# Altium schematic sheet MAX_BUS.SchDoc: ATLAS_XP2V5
size 558 x 431 mm; Organization: IMP Automatika d.o.o.; Revision: V5
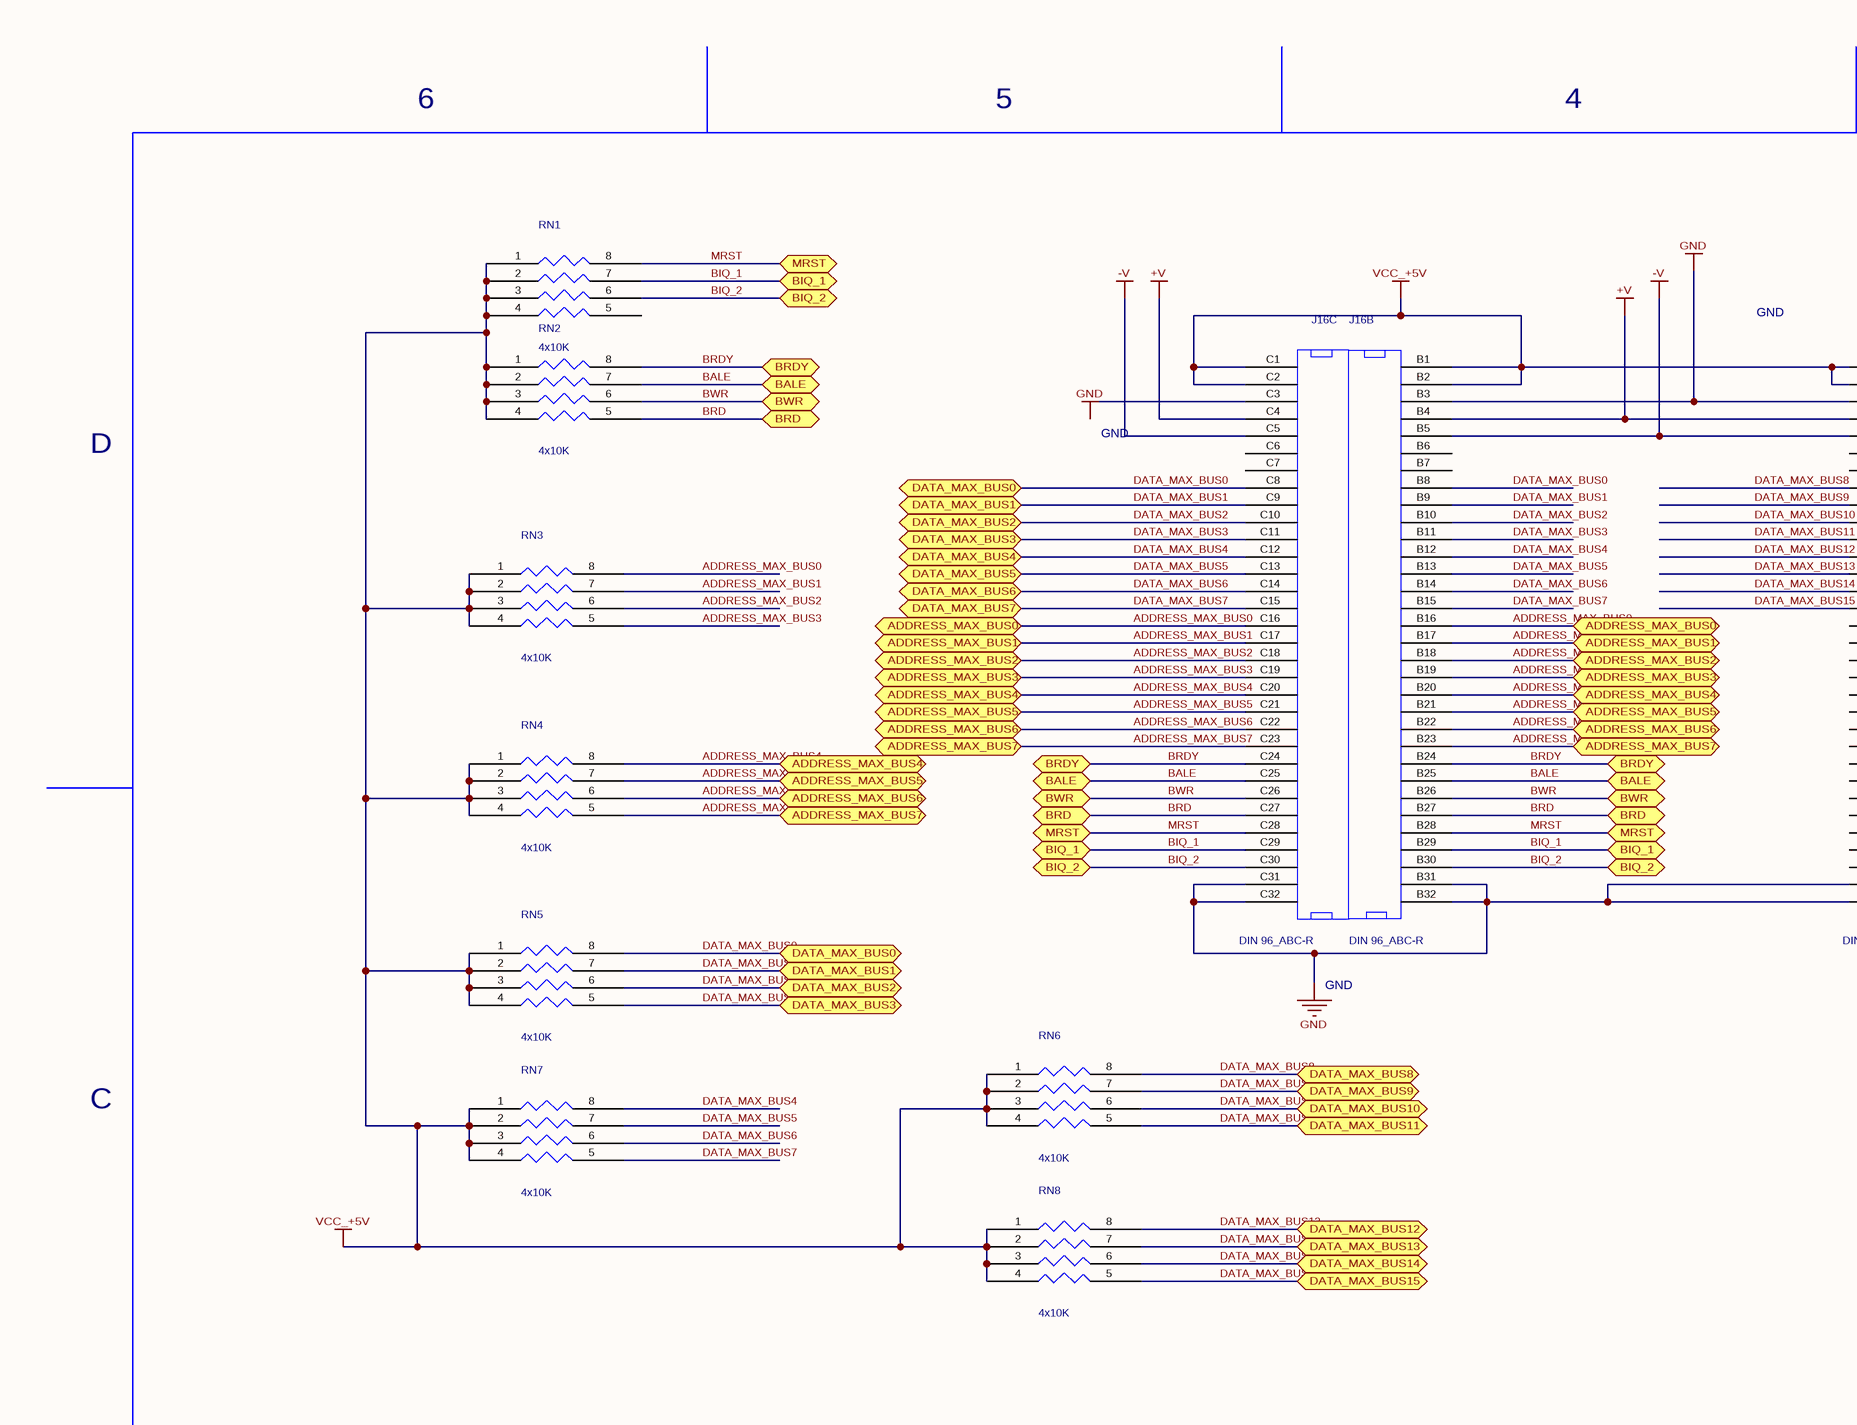
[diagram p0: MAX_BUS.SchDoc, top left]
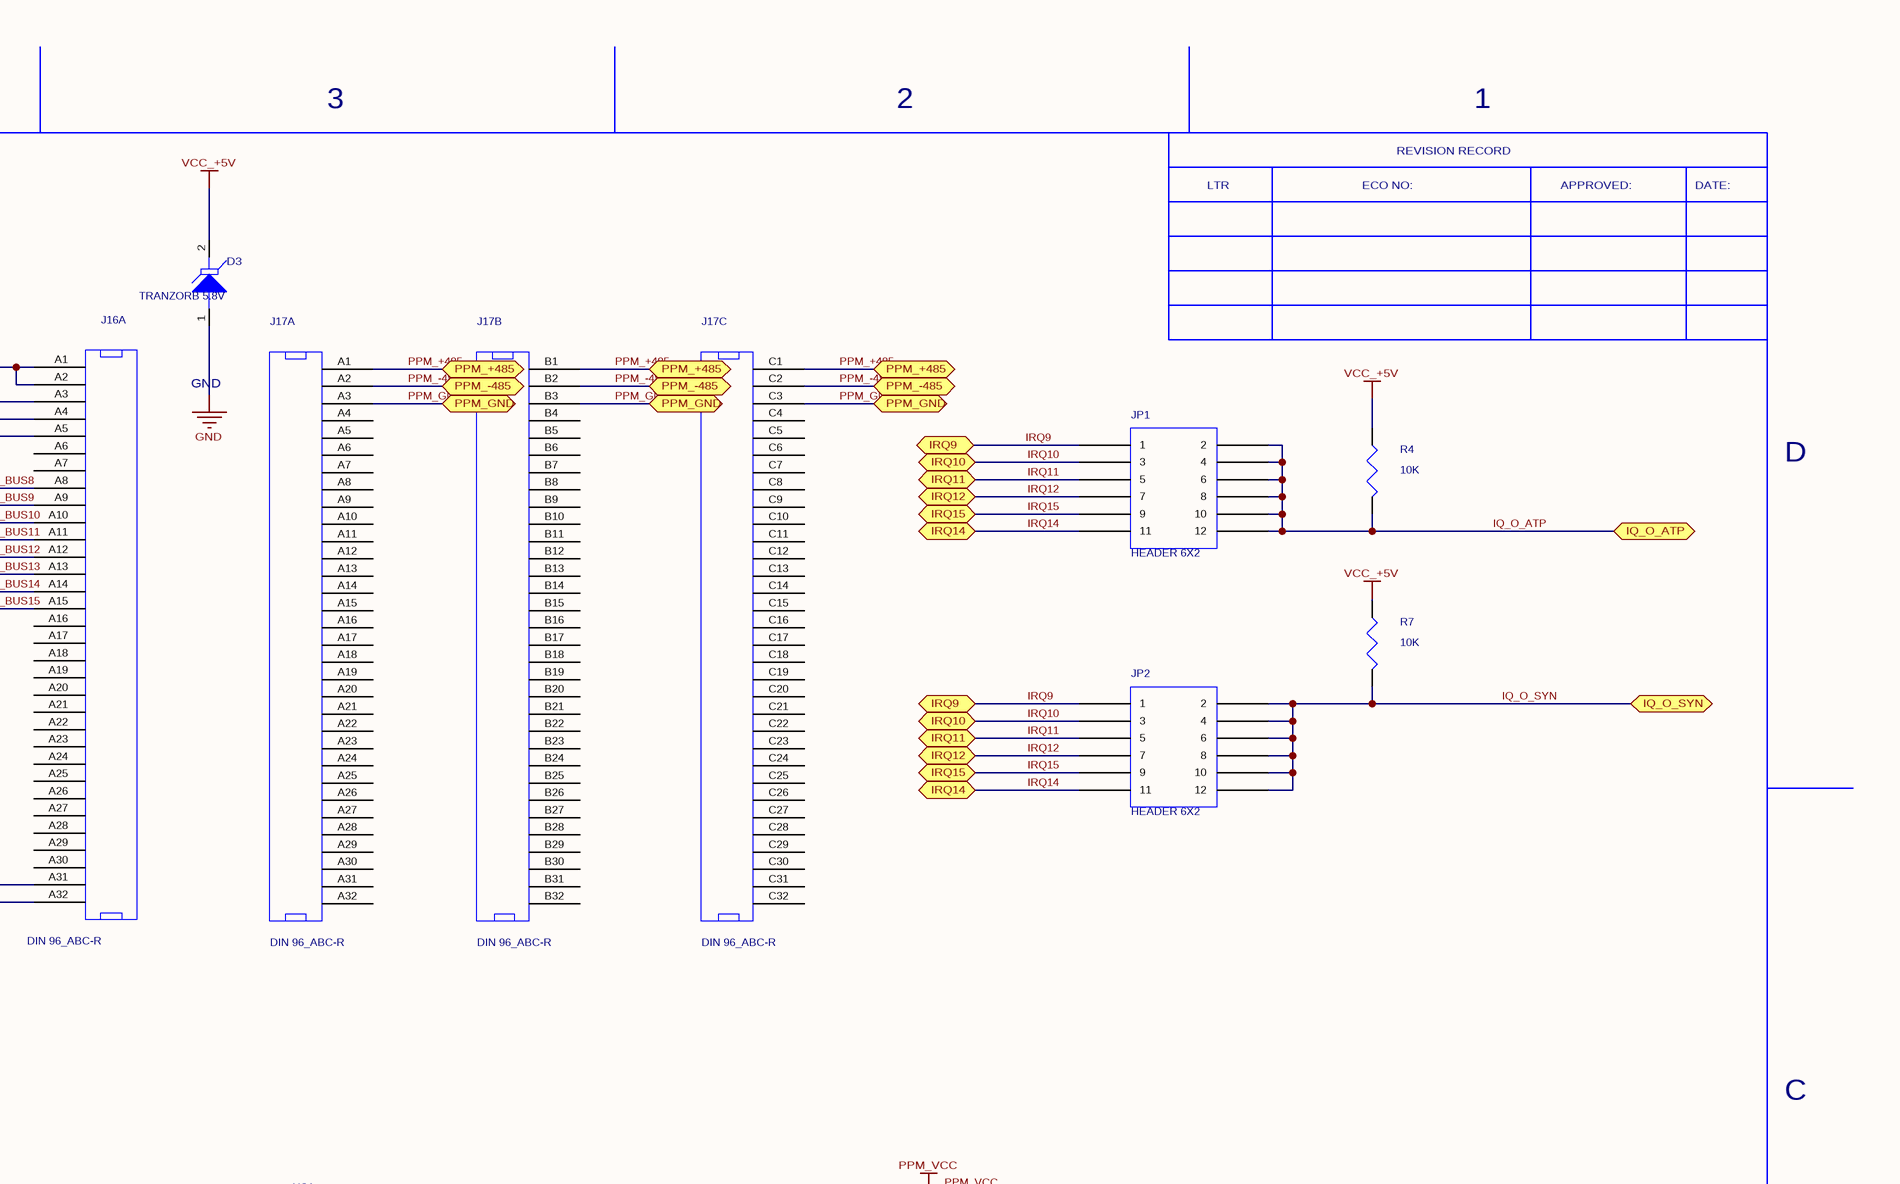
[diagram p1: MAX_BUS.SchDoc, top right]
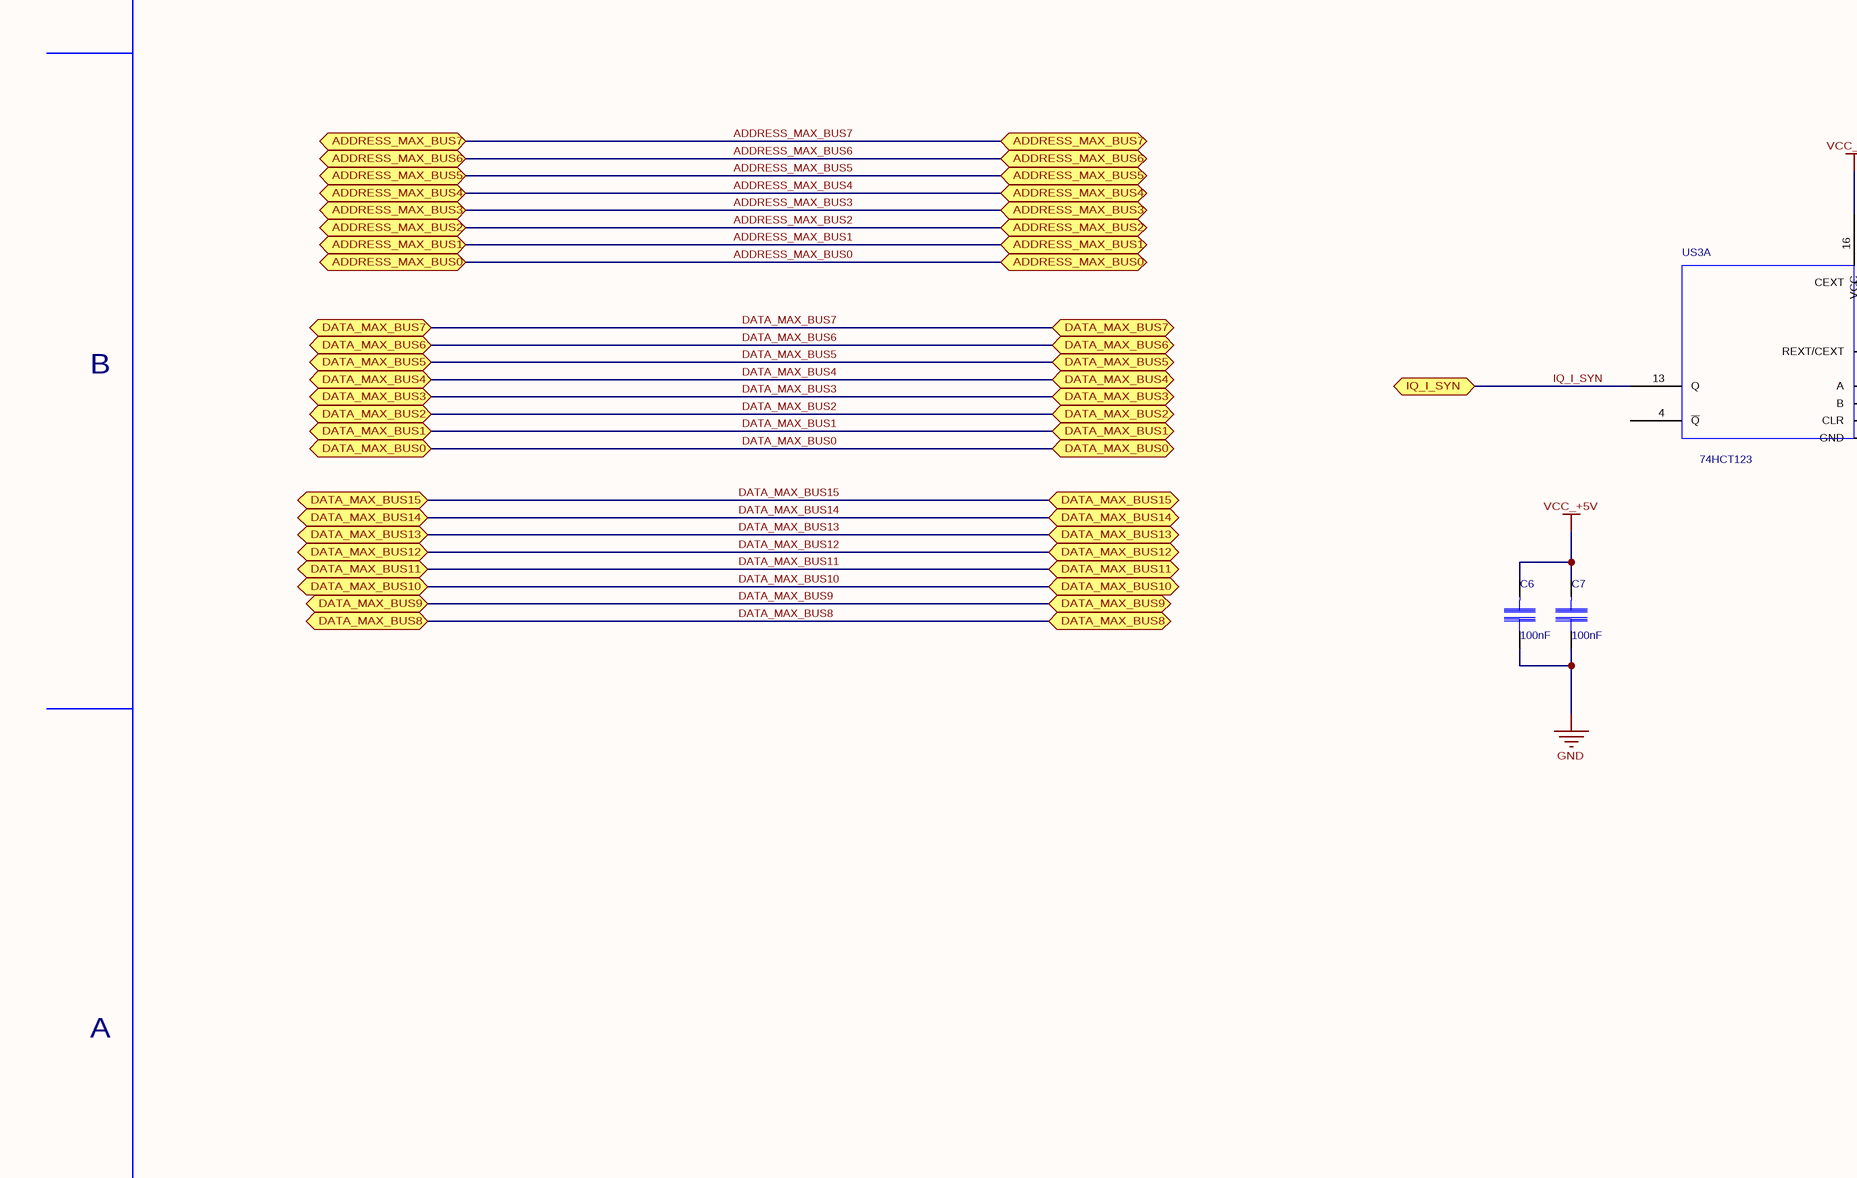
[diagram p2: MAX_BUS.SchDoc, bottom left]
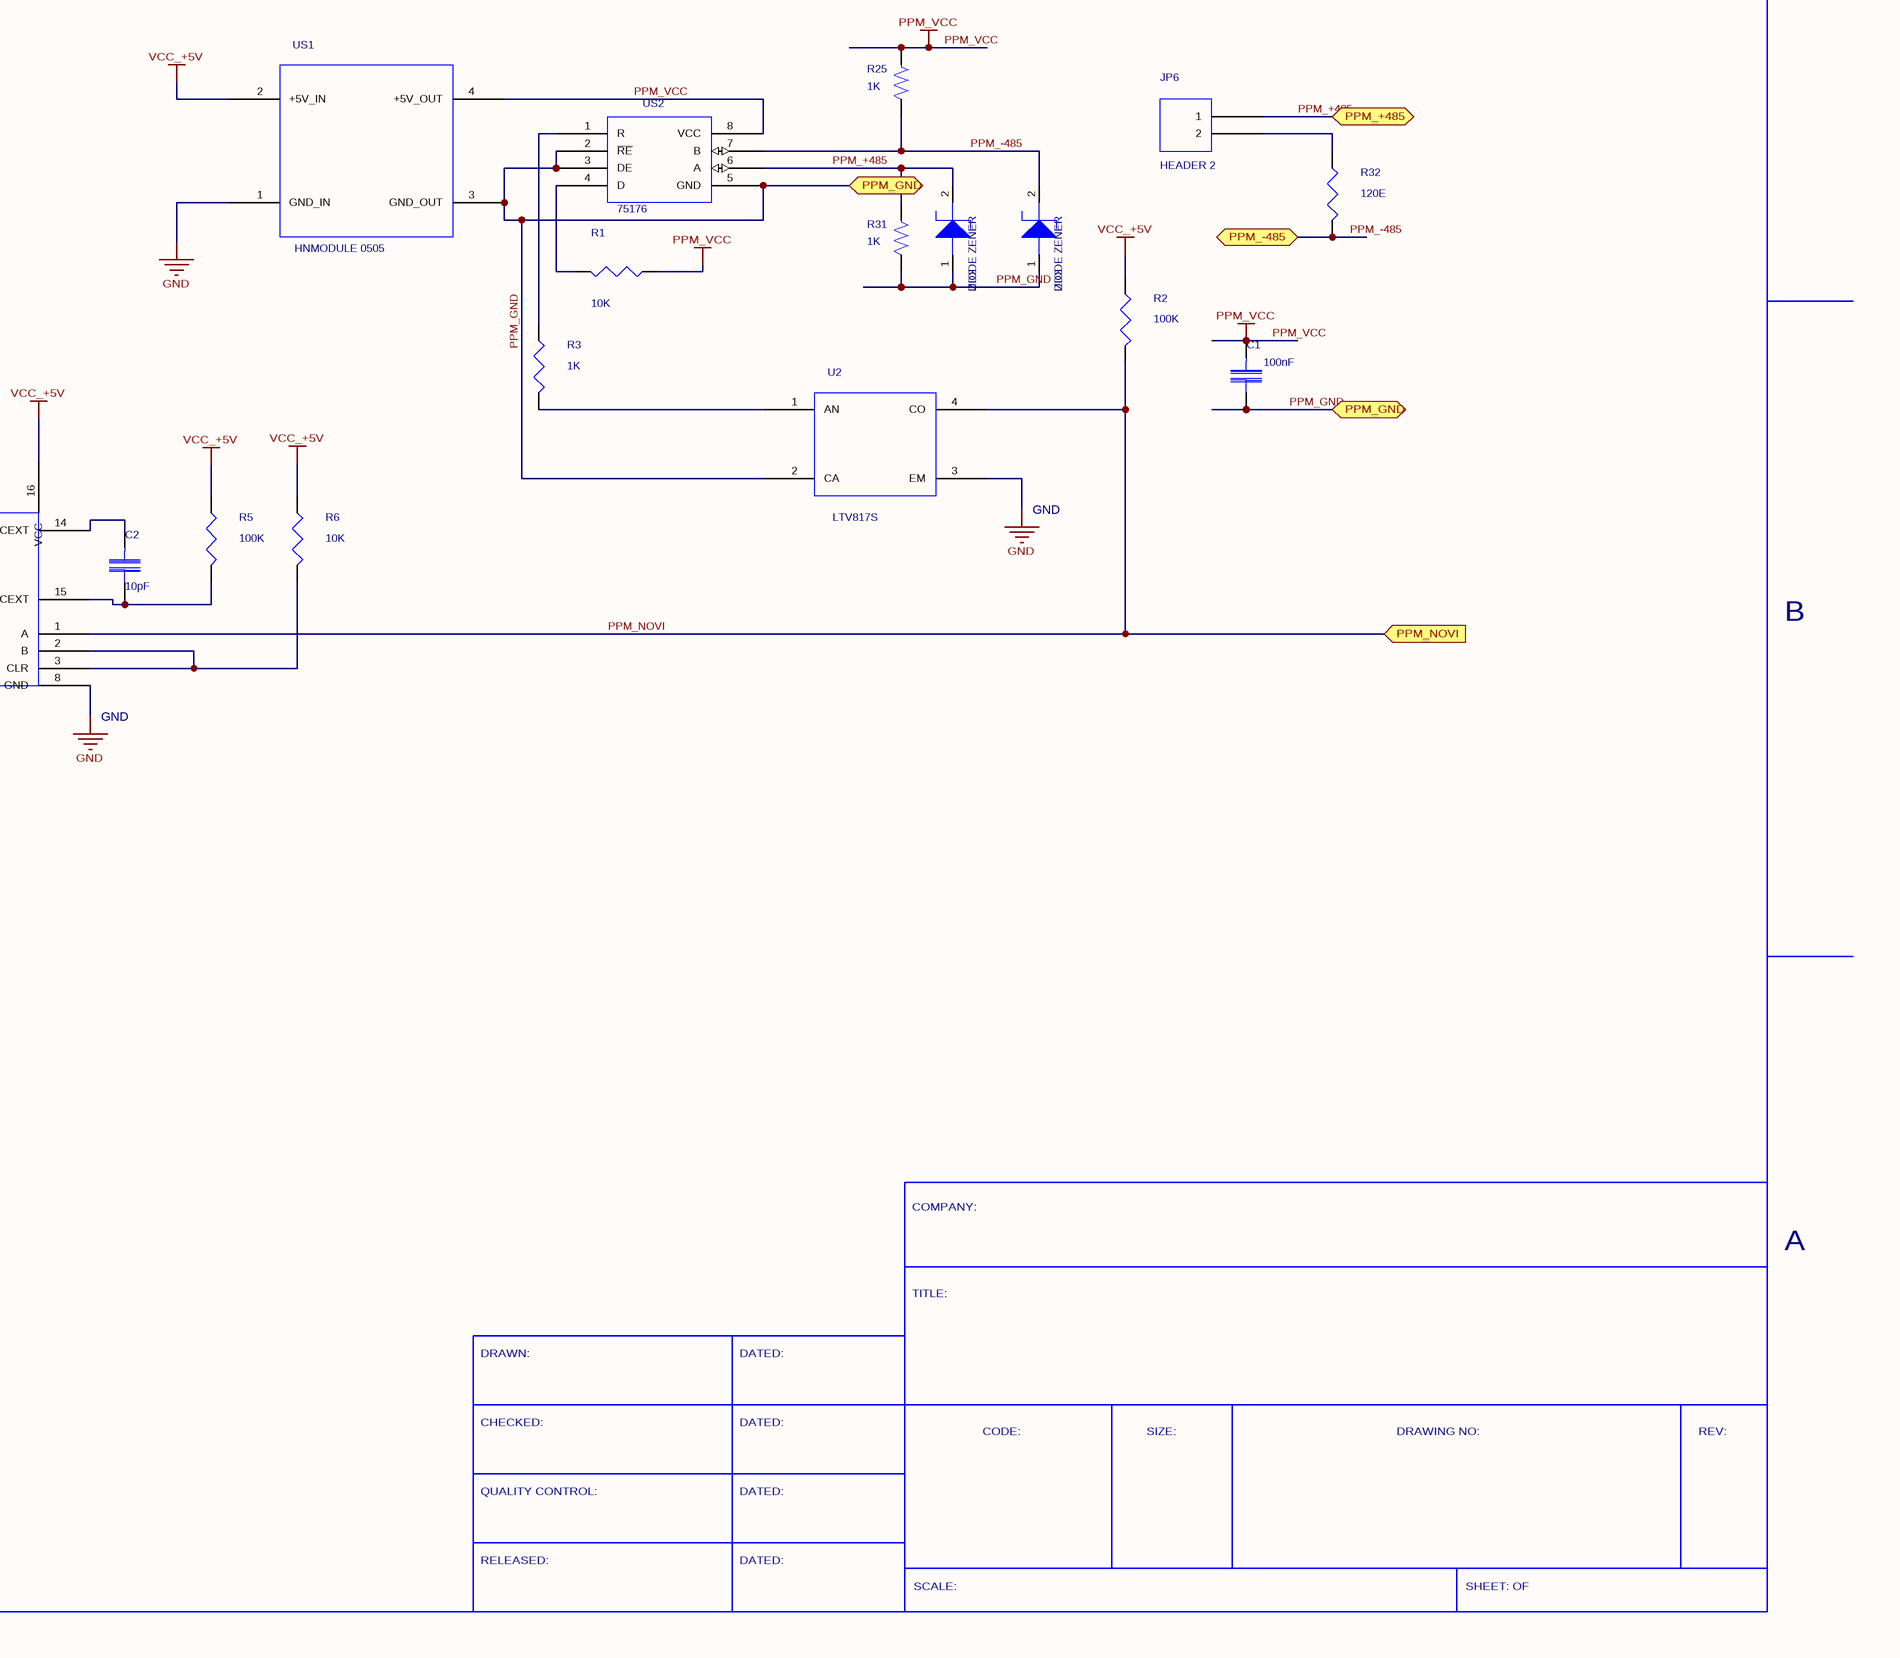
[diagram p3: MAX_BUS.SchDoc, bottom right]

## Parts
C1  value 100nF  [SM/C_0805]  (hidden comment: C)
C2  value 10pF  [SM/C_0805]  (hidden comment: C)
C6  value 100nF  [SM/C_0805]  (hidden comment: C)
C7  value 100nF  [SM/C_0805]  (hidden comment: C)
D3  value TRANZORB 5.8V  [SM/DO214AC_21]  (hidden comment: TRANZORB_0)
J16  value DIN 96_ABC-R  [DIN96_ABC/R]  (hidden comment: DIN_96_ABC-R)  (parts A,B,C of 3)
J17  value DIN 96_ABC-R  [DIN96_ABC/R]  (hidden comment: DIN_96_ABC-R)  (parts A,B,C of 3)
JP1  value HEADER 6X2  [BLKCON.100/VH/TM2OE/W.200/12]  (hidden comment: HEADER_6X2)
JP2  value HEADER 6X2  [BLKCON.100/VH/TM2OE/W.200/12]  (hidden comment: HEADER_6X2)
JP6  value HEADER 2  [JUMPER_100]  (hidden comment: HEADER_2)
R1  value 10K  [SM/R_1206]  (hidden comment: RESISTOR_2)
R2  value 100K  [SM/R_1206]  (hidden comment: RESISTOR_2)
R3  value 1K  [SM/R_1206]  (hidden comment: RESISTOR_2)
R4  value 10K  [SM/R_1206]  (hidden comment: RESISTOR_2)
R5  value 100K  [SM/R_1206]  (hidden comment: RESISTOR_2)
R6  value 10K  [SM/R_1206]  (hidden comment: RESISTOR_2)
R7  value 10K  [SM/R_1206]  (hidden comment: RESISTOR_2)
R25  value 1K  [SM/R_1206]  (hidden comment: R)
R31  value 1K  [SM/R_1206]  (hidden comment: R)
R32  value 120E  [SM/R_1206]  (hidden comment: RESISTOR_2)
RN1  value 4x10K  [SMD_RX4]  (hidden comment: RESAR_IS_4/SM)
RN2  value 4x10K  [SMD_RX4]  (hidden comment: RESAR_IS_4/SM)
RN3  value 4x10K  [SMD_RX4]  (hidden comment: RESAR_IS_4/SM)
RN4  value 4x10K  [SMD_RX4]  (hidden comment: RESAR_IS_4/SM)
RN5  value 4x10K  [SMD_RX4]  (hidden comment: RESAR_IS_4/SM)
RN6  value 4x10K  [SMD_RX4]  (hidden comment: RESAR_IS_4/SM)
RN7  value 4x10K  [SMD_RX4]  (hidden comment: RESAR_IS_4/SM)
RN8  value 4x10K  [SMD_RX4]  (hidden comment: RESAR_IS_4/SM)
U2  value LTV817S  [LTV814S]  (hidden comment: LTV-817_0)
US1  value HNMODULE 0505  [DCDC55]  (hidden comment: HNMODUL0505)
US2  75176  [SOG.050/8/WG.244/L.225]
US3  value 74HCT123  [SOG.050/16/WG.244/L.375]  (hidden comment: 74HC123_0)  (part A of 2)
ZD2  value DIODE ZENER  [SM/D_1206_21]  (hidden comment: DIODE_ZENER_0)
ZD3  value DIODE ZENER  [SM/D_1206_21]  (hidden comment: DIODE_ZENER_0)

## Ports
ADDRESS_MAX_BUS0 (bidir), ADDRESS_MAX_BUS1 (bidir), ADDRESS_MAX_BUS2 (bidir), ADDRESS_MAX_BUS3 (bidir), ADDRESS_MAX_BUS4 (bidir), ADDRESS_MAX_BUS5 (bidir), ADDRESS_MAX_BUS6 (bidir), ADDRESS_MAX_BUS7 (bidir), BALE (bidir), BIQ_1 (bidir), BIQ_2 (bidir), BRD (bidir), BRDY (bidir), BWR (bidir), DATA_MAX_BUS0 (bidir), DATA_MAX_BUS1 (bidir), DATA_MAX_BUS2 (bidir), DATA_MAX_BUS3 (bidir), DATA_MAX_BUS4 (bidir), DATA_MAX_BUS5 (bidir), DATA_MAX_BUS6 (bidir), DATA_MAX_BUS7 (bidir), DATA_MAX_BUS8 (bidir), DATA_MAX_BUS9 (bidir), DATA_MAX_BUS10 (bidir), DATA_MAX_BUS11 (bidir), DATA_MAX_BUS12 (bidir), DATA_MAX_BUS13 (bidir), DATA_MAX_BUS14 (bidir), DATA_MAX_BUS15 (bidir), IQ_I_SYN (bidir), IQ_O_ATP (bidir), IQ_O_SYN (bidir), IRQ9 (bidir), IRQ10 (bidir), IRQ11 (bidir), IRQ12 (bidir), IRQ14 (bidir), IRQ15 (bidir), MRST (bidir), PPM_+485 (bidir), PPM_-485 (bidir), PPM_GND (bidir), PPM_NOVI

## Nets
+V: J16.A4 J16.B4 J16.C4
-V: J16.A5 J16.B5 J16.C5
GND: C6.2 C7.2 D3.1(ANODE) J16.A3 J16.A31 J16.A32 J16.B3 J16.B31 J16.B32 J16.C3 J16.C31 J16.C32 U2.3(EM) US1.1(GND_IN) US3.8(GND)
PPM_VCC: C1.1 R1.1 R25.1 US1.4(+5V_OUT) US2.8(VCC)
VCC_+5V: C6.1 C7.1 D3.2(CATHODE) J16.A1 J16.A2 J16.B1 J16.B2 J16.C1 J16.C2 R2.1 R4.1 R5.1 R6.1 R7.1 RN1.1 RN1.2 RN1.3 RN1.4 RN2.1 RN2.2 RN2.3 RN2.4 RN3.1 RN3.2 RN3.3 RN3.4 RN4.1 RN4.2 RN4.3 RN4.4 RN5.1 RN5.2 RN5.3 RN5.4 RN6.1 RN6.2 RN6.3 RN6.4 RN7.1 RN7.2 RN7.3 RN7.4 RN8.1 RN8.2 RN8.3 RN8.4 US1.2(+5V_IN) US3.16(VCC)
ADDRESS_MAX_BUS0: J16.B16 J16.C16 RN3.8 ; port ADDRESS_MAX_BUS0
ADDRESS_MAX_BUS1: J16.B17 J16.C17 RN3.7 ; port ADDRESS_MAX_BUS1
ADDRESS_MAX_BUS2: J16.B18 J16.C18 RN3.6 ; port ADDRESS_MAX_BUS2
ADDRESS_MAX_BUS3: J16.B19 J16.C19 RN3.5 ; port ADDRESS_MAX_BUS3
ADDRESS_MAX_BUS4: J16.B20 J16.C20 RN4.8 ; port ADDRESS_MAX_BUS4
ADDRESS_MAX_BUS5: J16.B21 J16.C21 RN4.7 ; port ADDRESS_MAX_BUS5
ADDRESS_MAX_BUS6: J16.B22 J16.C22 RN4.6 ; port ADDRESS_MAX_BUS6
ADDRESS_MAX_BUS7: J16.B23 J16.C23 RN4.5 ; port ADDRESS_MAX_BUS7
BALE: J16.B25 J16.C25 RN2.7 ; port BALE
BIQ_1: J16.B29 J16.C29 RN1.7 ; port BIQ_1
BIQ_2: J16.B30 J16.C30 RN1.6 ; port BIQ_2
BRD: J16.B27 J16.C27 RN2.5 ; port BRD
BRDY: J16.B24 J16.C24 RN2.8 ; port BRDY
BWR: J16.B26 J16.C26 RN2.6 ; port BWR
DATA_MAX_BUS0: J16.B8 J16.C8 RN5.8 ; port DATA_MAX_BUS0
DATA_MAX_BUS1: J16.B9 J16.C9 RN5.7 ; port DATA_MAX_BUS1
DATA_MAX_BUS2: J16.B10 J16.C10 RN5.6 ; port DATA_MAX_BUS2
DATA_MAX_BUS3: J16.B11 J16.C11 RN5.5 ; port DATA_MAX_BUS3
DATA_MAX_BUS4: J16.B12 J16.C12 RN7.8 ; port DATA_MAX_BUS4
DATA_MAX_BUS5: J16.B13 J16.C13 RN7.7 ; port DATA_MAX_BUS5
DATA_MAX_BUS6: J16.B14 J16.C14 RN7.6 ; port DATA_MAX_BUS6
DATA_MAX_BUS7: J16.B15 J16.C15 RN7.5 ; port DATA_MAX_BUS7
DATA_MAX_BUS8: J16.A8 RN6.8 ; port DATA_MAX_BUS8
DATA_MAX_BUS9: J16.A9 RN6.7 ; port DATA_MAX_BUS9
DATA_MAX_BUS10: J16.A10 RN6.6 ; port DATA_MAX_BUS10
DATA_MAX_BUS11: J16.A11 RN6.5 ; port DATA_MAX_BUS11
DATA_MAX_BUS12: J16.A12 RN8.8 ; port DATA_MAX_BUS12
DATA_MAX_BUS13: J16.A13 RN8.7 ; port DATA_MAX_BUS13
DATA_MAX_BUS14: J16.A14 RN8.6 ; port DATA_MAX_BUS14
DATA_MAX_BUS15: J16.A15 RN8.5 ; port DATA_MAX_BUS15
IQ_I_SYN: US3.13(Q) ; port IQ_I_SYN
IQ_O_ATP: JP1.2 JP1.4 JP1.6 JP1.8 JP1.10 JP1.12 R4.2 ; port IQ_O_ATP
IQ_O_SYN: JP2.2 JP2.4 JP2.6 JP2.8 JP2.10 JP2.12 R7.2 ; port IQ_O_SYN
IRQ9: JP1.1 JP2.1 ; port IRQ9
IRQ10: JP1.3 JP2.3 ; port IRQ10
IRQ11: JP1.5 JP2.5 ; port IRQ11
IRQ12: JP1.7 JP2.7 ; port IRQ12
IRQ14: JP1.11 JP2.11 ; port IRQ14
IRQ15: JP1.9 JP2.9 ; port IRQ15
MRST: J16.B28 J16.C28 RN1.8 ; port MRST
PPM_+485: J17.A1 J17.B1 J17.C1 JP6.1 R31.1 US2.6(A) ZD2.2(CATHODE) ; port PPM_+485
PPM_-485: J17.A2 J17.B2 J17.C2 R25.2 R32.2 US2.7(B) ZD3.2(CATHODE) ; port PPM_-485
PPM_GND: C1.2 J17.A3 J17.B3 J17.C3 R31.2 U2.2(CA) US1.3(GND_OUT) US2.2(~{RE}) US2.3(DE) US2.5(GND) ZD2.1(ANODE) ZD3.1(ANODE) ; port PPM_GND
PPM_NOVI: R2.2 U2.4(CO) US3.1(A) ; port PPM_NOVI
NetC2_1: C2.1 US3.14(CEXT)
NetC2_2: C2.2 R5.2 US3.15(REXT/CEXT)
NetJP6_2: JP6.2 R32.1
NetR1_2: R1.2 US2.4(D)
NetR3_1: R3.1 US2.1(R)
NetR3_2: R3.2 U2.1(AN)
NetR6_2: R6.2 US3.2(B) US3.3(CLR)

Not connected (* = marked no-connect by the designer): J16 A6 A7 A16 A17 A18 A19 A20 A21 A22 A23 A24 A25 A26 A27 A28 A29 A30 B6 B7 C6 C7; J17 A4 A5 A6 A7 A8 A9 A10 A11 A12 A13 A14 A15 A16 A17 A18 A19 A20 A21 A22 A23 A24 A25 A26 A27 A28 A29 A30 A31 A32 B4 B5 B6 B7 B8 B9 B10 B11 B12 B13 B14 B15 B16 B17 B18 B19 B20 B21 B22 B23 B24 B25 B26 B27 B28 B29 B30 B31 B32 C4 C5 C6 C7 C8 C9 C10 C11 C12 C13 C14 C15 C16 C17 C18 C19 C20 C21 C22 C23 C24 C25 C26 C27 C28 C29 C30 C31 C32; RN1 5; US3 4(~{Q})

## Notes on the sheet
- 6
- 5
- 4
- 3
- 2
- 1
- LTR
- ECO NO:
- REVISION RECORD
- APPROVED:
- DATE:
- GND
- D
- C
- B
- (near US3) GND
- COMPANY:
- A
- TITLE:
- DRAWN:
- DATED:
- CHECKED:
- CODE:
- SIZE:
- DRAWING NO:
- REV:
- QUALITY CONTROL:
- RELEASED:
- SCALE:
- SHEET: OF

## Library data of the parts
C1 C2 C6 C7 = C: Source_Path: D:\ORCADWIN\CAPTURE\ATP_LATT_01\ATP_00.OLB; SDTSourceLibName: C:\WINDOWS\TEMP\ATP_00.LIB
D3 = TRANZORB_0: Source_Path: C:\CADENCE\PSD_15.1\TOOLS\ATLAS_ITA\ATLAS_ITA.DSN
J16 J17 = DIN_96_ABC-R: Source_Path: C:\ORCAD\ORCAD_10.5\TOOLS\CAPTURE\LIBRARY\CONNECTOR.OLB
JP1 JP2 = HEADER_6X2: Source_Path: D:\ORCADWIN\CAPTURE\PTA\PC2A_00.OLB; SDTSourceLibName: C:\WINDOWS\TEMP\PC2A_00.LIB
JP6 = HEADER_2: Source_Path: D:\ORCADWIN\CAPTURE\PTA\PC2A_00.OLB; SDTSourceLibName: C:\WINDOWS\TEMP\PC2A_00.LIB
R1-R7 R32 = RESISTOR_2: Source_Path: C:\CADENCE\PSD_15.1\TOOLS\CAPTURE\LIBRARY\DISCRETE.OLB
R25 R31 = R: Source_Path: C:\ORCAD\ORCAD_10.0\TOOLS\CAPTURE\LIBRARY\PSPICE\ANALOG.OLB; DIST: FLAT; PSpiceTemplate: R^@REFDES %1 %2 ?TOLERANCE¦R^@REFDES¦ @VALUE  ?TOLERANCE¦\n.model R^@REFDES RES R=1 DEV=@TOLERANCE%¦; VOLTAGE: RVMAX; SLOPE: RSMAX; MAX_TEMP: RTMAX; POWER: RMAX
RN1-RN8 = RESAR_IS_4/SM: Source_Path: C:\ORCAD\ORCAD_10.5\TOOLS\CAPTURE\LIBRARY\DISCRETE.OLB
U2 = LTV-817_0: Source_Path: E:\MILOS\PROJECTS\ATLAS_XP\ATLAS_XP.DSN
US1 = HNMODUL0505: Source_Path: C:\PROJECTS\ATLAS_ITA\LIBRARY1.OLB
US2 = 75176: Source_Path: C:\ORCADESP\SDT\LIBRARY\TARIFA_O.OLB
US3 = 74HC123_0: Source_Path: E:\MILOS\PROJECTS\ATLAS_XP\ATLAS_XP.DSN
ZD2 ZD3 = DIODE_ZENER_0: Source_Path: C:\PROJECTS\VHDL_PROJEKTI\BIS32W_ORCAD\BIS32W\BIS32_16.DSN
